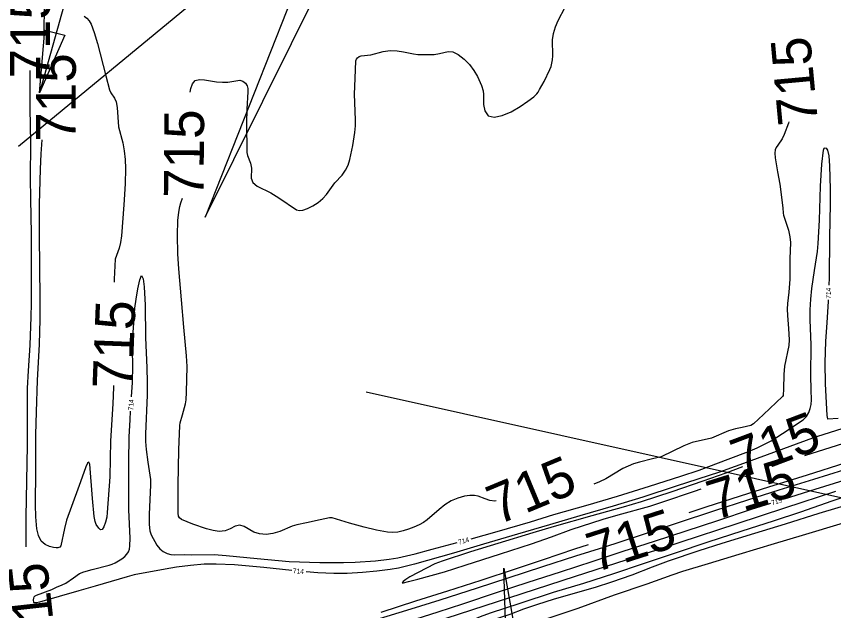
# Model space of a CAD drawing. Extents: x -468563856 to 36492962, y -306094093 to 11899197.
# Drawn here: x 1821764 to 1822443, y 531121 to 531615 of the extents above; entities that cross this region are included whole.
import ezdxf

# ---------------------------------------------------------------- set-up
doc = ezdxf.new("R2010")
doc.units = 0
for name, color, linetype in [('DT_X_Contour_Minor', 7, 'Continuous'), ('Level 14', 7, 'Continuous'), ('Level 19', 7, 'Continuous'), ('Level 40', 7, 'Continuous'), ('SH_Text', 7, 'Continuous')]:
    doc.layers.add(name, color=color, linetype=linetype)

msp = doc.modelspace()

# ---------------------------------------------------------------- linework, layer by layer
at = {"layer": 'DT_X_Contour_Minor'}
for points in [[(1821787.24, 531595.3), (1821787.25, 531596.38), (1821787.46, 531628.02)], [(1821908.51, 531551.65), (1821908.92, 531554.5), (1821910.29, 531558.61), (1821912.61, 531561.28), (1821916.06, 531562.18), (1821920.4, 531561.82), (1821930.38, 531560.22), (1821935.33, 531559.85), (1821939.83, 531559.99), (1821949.68, 531561.52), (1821952.22, 531560.68), (1821954.32, 531559.04), (1821955.74, 531556.94), (1821956.35, 531554.61), (1821956.36, 531551.73), (1821955.51, 531537.41), (1821955.32, 531526.08), (1821955.52, 531501.55), (1821956.19, 531499.05), (1821958.6, 531492.51), (1821959.31, 531488.53), (1821959.21, 531480.09), (1821960.5, 531476.44), (1821963.97, 531473.57), (1821975.51, 531467.87), (1821982.15, 531463.89), (1821996.74, 531453.97), (1821999.27, 531453.21), (1822002.05, 531453.59), (1822005.9, 531454.92), (1822010.39, 531457.05), (1822014.83, 531459.87), (1822018.61, 531463.19), (1822021.61, 531466.6), (1822028.71, 531476.2), (1822034.54, 531482.67), (1822037.43, 531486.67), (1822039.59, 531491), (1822041.14, 531495.78), (1822043.52, 531507.18), (1822045.24, 531518.04), (1822045.78, 531523.5), (1822045.74, 531528.63), (1822044.98, 531550), (1822045.34, 531563.04), (1822046, 531577.75), (1822046.5, 531579.03), (1822047.42, 531580.19), (1822048.74, 531581.12), (1822050.38, 531581.7), (1822058.48, 531582.7), (1822068.8, 531585.3), (1822074.66, 531586.13), (1822080.34, 531585.96), (1822085.58, 531585.11), (1822093.98, 531583.38), (1822097.54, 531582.96), (1822106.1, 531582.74), (1822111.05, 531582.99), (1822115.63, 531583.66), (1822122.79, 531585.46), (1822126.52, 531585.04), (1822131.03, 531582.81), (1822135.89, 531579.11), (1822140.43, 531574.49), (1822144.13, 531569.51), (1822146.95, 531564.64), (1822150.34, 531557.01), (1822151.64, 531552.78), (1822151.95, 531549.65), (1822152.11, 531541.47), (1822153.11, 531535.99), (1822155.81, 531531.95), (1822160.78, 531530.79), (1822167.44, 531532.19), (1822174.92, 531535.38), (1822182.36, 531539.6), (1822188.92, 531543.99), (1822193.79, 531547.72), (1822196.45, 531550.15), (1822197.53, 531551.6), (1822198.51, 531553.67), (1822202.34, 531560.47), (1822207.15, 531570.4), (1822208.1, 531572.97), (1822208.78, 531575.56), (1822209.24, 531578.48), (1822209.47, 531581.85), (1822209.31, 531595.09), (1822210.03, 531600.35), (1822211.75, 531605.79), (1822214.05, 531611.03), (1822219.8, 531622.07)], [(1821820.38, 531614.78), (1821822.55, 531612.98), (1821824.56, 531610.96), (1821826.29, 531608.02), (1821828.84, 531601.16), (1821831.36, 531591.98), (1821838.45, 531565.27), (1821841.44, 531553.66), (1821842.58, 531551.03), (1821845.72, 531546.7), (1821847.06, 531543.49), (1821847.84, 531538.82), (1821848.97, 531522.69), (1821852.5, 531509.48), (1821853.74, 531502.84), (1821854.48, 531495.53), (1821854.77, 531488.13), (1821854.6, 531475.45), (1821853.47, 531458.08), (1821851.46, 531432.18), (1821850.61, 531426.82), (1821849.41, 531421.97), (1821846.22, 531412.79), (1821845.32, 531396.11), (1821845.28, 531393.87)], [(1821775.34, 531569.64), (1821775.25, 531553.19), (1821775.25, 531538.03), (1821775.75, 531509.5), (1821775.61, 531480.22), (1821775.79, 531462.92), (1821776.29, 531433.8), (1821776.49, 531405.07), (1821776.35, 531375.95), (1821776.25, 531364.83), (1821775.22, 531341.52), (1821773.88, 531320.01), (1821773.14, 531305.57), (1821773.06, 531286.82), (1821773.04, 531258.18), (1821772.58, 531228.63), (1821771.9, 531198.39), (1821772.09, 531173.85)], [(1822405.67, 531527.01), (1822405.3, 531525.71), (1822401.84, 531516.46), (1822400.01, 531512.72), (1822396.54, 531507.51), (1822395.18, 531505.55), (1822394.24, 531503.57), (1822393.84, 531500.96), (1822394.1, 531497.05), (1822396.24, 531485.48), (1822398.24, 531475.22), (1822400.49, 531455.49), (1822400.86, 531451.01), (1822401.24, 531449.3), (1822405.25, 531436.82), (1822406.48, 531431.39), (1822406.87, 531426.72), (1822406.34, 531413.14), (1822406.43, 531396.2), (1822405.71, 531385.38), (1822404.61, 531376.15), (1822404.32, 531371.4), (1822404.41, 531366.14), (1822405.27, 531355.35), (1822405.71, 531350.51), (1822405.88, 531345.91), (1822405.53, 531341.21), (1822402.09, 531324), (1822401.42, 531317.07), (1822401.08, 531305.18), (1822400.92, 531299.64), (1822400.25, 531298.77), (1822384.55, 531283.79), (1822376.2, 531275.93), (1822374.13, 531274.67), (1822366.95, 531273.14), (1822361.27, 531271.85), (1822355.47, 531270.11), (1822341.32, 531264.13), (1822325.19, 531260.53), (1822318.29, 531257.75), (1822299.68, 531248.73), (1822292.25, 531246.93), (1822281.49, 531244.28), (1822276.63, 531242.76), (1822272.19, 531241), (1822267.85, 531238.83), (1822253.59, 531230.37), (1822248.44, 531227.81), (1822243.73, 531225.86)], [(1821844.84, 531307.94), (1821844.86, 531306.38), (1821844.22, 531292.62), (1821842.23, 531262.06), (1821841.64, 531232.12), (1821839.64, 531202.28), (1821839.11, 531198.46), (1821838.13, 531194.3), (1821836.82, 531190.52), (1821835.37, 531188.18), (1821833.95, 531187.99), (1821832.62, 531189.27), (1821830.4, 531192.56), (1821829.49, 531194.81), (1821828.67, 531199.01), (1821827.21, 531214.03), (1821825.08, 531242.47), (1821824.38, 531244.31), (1821823.23, 531243.27), (1821821.82, 531240.25), (1821817.4, 531228.01), (1821815.26, 531221.69), (1821805.78, 531196.05), (1821803.98, 531189.04), (1821801.05, 531174.84), (1821800.08, 531173.61), (1821798.69, 531173.12), (1821797.26, 531173.1), (1821794.95, 531173.38), (1821791.64, 531174.1), (1821787.95, 531175.7), (1821784.7, 531178.69), (1821782.51, 531183.32), (1821781.25, 531188.83), (1821780.27, 531198.81), (1821780.13, 531208.77), (1821780.21, 531237.36), (1821780.4, 531266.8), (1821780.75, 531286), (1821781.77, 531311.94), (1821783.21, 531342.35), (1821783.79, 531362.65), (1821783.76, 531380.37), (1821783.57, 531406.32), (1821783.45, 531432.48), (1821783.43, 531458.63), (1821784.12, 531487.67), (1821784.63, 531500.47), (1821785.45, 531512.07)], [(1822141.86, 531180.57), (1822163.32, 531186.61), (1822191.15, 531194.69), (1822210.54, 531200.63), (1822239.03, 531208.78), (1822263.34, 531215.89), (1822289.98, 531224.16), (1822315.78, 531232.45), (1822331.14, 531237.68), (1822355.29, 531246.71), (1822371.97, 531252.98), (1822379.19, 531256.05), (1822385.43, 531259.06), (1822390.9, 531262.05), (1822400.36, 531268.08), (1822417.35, 531279.29), (1822420.13, 531282.26), (1822422.08, 531285.4), (1822423.34, 531288.72), (1822424.05, 531292.22), (1822424.35, 531295.94), (1822424.2, 531304.41), (1822423.92, 531316.33), (1822424.11, 531341.73), (1822423.22, 531362.4), (1822423.4, 531370.68), (1822423.93, 531379.65), (1822424.74, 531388.49), (1822426.81, 531403.37), (1822429.43, 531419.12), (1822430.07, 531425.85), (1822431.13, 531445.25), (1822431.79, 531473.53), (1822433, 531491.66), (1822434.29, 531503.52), (1822434.87, 531505.07), (1822435.62, 531505.28), (1822436.62, 531505.02), (1822437.72, 531503.29), (1822438.71, 531498.64), (1822439.41, 531490.29), (1822440.04, 531470.93), (1822439.98, 531458.84), (1822439.34, 531430.85), (1822438.95, 531397.28), (1822438.73, 531391.13)], [(1822162.6, 531212.01), (1822161.46, 531211.9), (1822157.16, 531212.47), (1822153.55, 531213.68), (1822147.55, 531216.02), (1822144.5, 531216.55), (1822140.8, 531216.53), (1822136.16, 531215.86), (1822130.85, 531214.42), (1822125.3, 531212.04), (1822119.94, 531208.69), (1822115.08, 531204.9), (1822105.25, 531196.18), (1822102.28, 531194.14), (1822098.53, 531192.13), (1822094.18, 531190.2), (1822089.64, 531188.47), (1822085.22, 531187.08), (1822080.9, 531186.14), (1822076.63, 531185.76), (1822072.32, 531186.01), (1822063.26, 531187.72), (1822053.01, 531190.1), (1822040.63, 531193.61), (1822026.4, 531197.94), (1822024.08, 531198.03), (1822016.31, 531196.29), (1822005.13, 531193.69), (1821997.1, 531192.15), (1821993.16, 531190.94), (1821982.86, 531186.72), (1821977.11, 531184.94), (1821971.47, 531184.19), (1821966.15, 531184.58), (1821961.33, 531186.08), (1821953.28, 531190.79), (1821949.58, 531191.86), (1821945.78, 531190.92), (1821941.74, 531188.9), (1821937.39, 531187.13), (1821932.65, 531186.64), (1821927.5, 531187.35), (1821921.95, 531188.87), (1821910.6, 531192.84), (1821901.27, 531196.72), (1821899.48, 531197.99), (1821898.66, 531199.28), (1821898.48, 531201.76), (1821898.57, 531225.19), (1821899.11, 531254.43), (1821899.88, 531274.66), (1821900.19, 531277), (1821902.04, 531283.61), (1821904.53, 531292.56), (1821905.17, 531295.86), (1821905.54, 531302.25), (1821905.97, 531323.64), (1821905.27, 531332.66), (1821903.11, 531356.38), (1821901.34, 531379), (1821898.99, 531404.77), (1821898.22, 531417.18), (1821897.95, 531432.74), (1821898.34, 531444.93), (1821899.08, 531451.76), (1821899.87, 531456.49), (1821900.65, 531459.54), (1821902.21, 531463.62)], [(1821859.79, 531298.45), (1821860.58, 531310.28), (1821860.73, 531324.49), (1821860.52, 531337.24), (1821861.13, 531351.84), (1821862.61, 531372.12), (1821863.54, 531379.62), (1821864.94, 531388.27), (1821866.57, 531395.79), (1821868.1, 531399.23), (1821869.29, 531396.61), (1821870.12, 531389.84), (1821870.96, 531374.76), (1821871.49, 531347.79), (1821872.41, 531322.58), (1821872.85, 531310.58), (1821872.65, 531299.99), (1821871.27, 531267.73), (1821871.3, 531261.42), (1821871.85, 531254.74), (1821873.3, 531244.19), (1821875.37, 531229.79), (1821875.48, 531225.42), (1821874.48, 531200.64), (1821874.49, 531192.45), (1821875.05, 531187.16), (1821876.07, 531183.96), (1821880.9, 531175.23), (1821883.23, 531172.27), (1821886.08, 531169.98), (1821889.25, 531168.42), (1821892.45, 531167.56), (1821895.5, 531167.31), (1821903.78, 531167.55), (1821909.67, 531167.34), (1821928.35, 531167.53), (1821938.44, 531166.73), (1821964.12, 531164.16), (1821990.55, 531161.76), (1822016.22, 531160.97), (1822035.88, 531160.81), (1822045.42, 531161.03), (1822062.33, 531162.21), (1822073.59, 531163.56), (1822080.84, 531164.85), (1822095.19, 531168.11), (1822109.52, 531171.87), (1822130.28, 531177.43)], [(1822322.87, 531202.48), (1822336.81, 531207.01), (1822365.37, 531216.17), (1822388.93, 531223.69), (1822421, 531233.73), (1822452.26, 531243.68), (1822481.68, 531253.08), (1822514.64, 531263.6), (1822539.51, 531271.47), (1822570.49, 531281.53), (1822598.74, 531290.73), (1822624.33, 531299.06), (1822655.31, 531309.53), (1822683.2, 531319.25), (1822708.28, 531327.91), (1822740.17, 531338.35), (1822768.69, 531347.69), (1822794.6, 531356.17), (1822825.94, 531366.22), (1822854.4, 531375.36), (1822879.45, 531383.5), (1822889, 531386.64)], [(1822916.04, 531379.03), (1822912.4, 531377.88), (1822886.75, 531369.58), (1822859.99, 531360.88), (1822834.76, 531352.82), (1822802.38, 531342.4), (1822795.74, 531340.2), (1822766.06, 531331.14), (1822737.42, 531322.01), (1822709.4, 531312.99), (1822679.09, 531303.03), (1822651.2, 531293.87), (1822621.81, 531284.49), (1822593.01, 531275.06), (1822564.14, 531265.62), (1822535.53, 531256.41), (1822506.87, 531247.23), (1822479.66, 531238.22), (1822451.29, 531229.02), (1822427.15, 531221.52), (1822401.81, 531213.59)], [(1822438.29, 531379.14), (1822438.25, 531378), (1822437.16, 531359.99), (1822436.09, 531344.62), (1822435.52, 531326.86), (1822435.8, 531309.39), (1822437.27, 531283), (1822437.75, 531280.24), (1822438.09, 531280.09), (1822446.43, 531280.76)], [(1822419, 531249.64), (1822430.24, 531253.3), (1822450.44, 531259.76), (1822479.49, 531269.06), (1822508.08, 531278.13), (1822538.61, 531287.87), (1822568.86, 531297.55), (1822599.12, 531307.3), (1822616.53, 531313.24), (1822648.77, 531324.28), (1822679.48, 531334.41), (1822706.41, 531343.45), (1822730.03, 531351.17), (1822759, 531360.25), (1822783.74, 531368.07)], [(1821992.96, 531154.24), (1821969.56, 531156.72), (1821945.33, 531158.81), (1821930, 531159.39), (1821920.13, 531159.34), (1821908.69, 531158.44), (1821897.06, 531157.04), (1821887.56, 531155.4), (1821862.06, 531150.48), (1821856.12, 531149.02), (1821829.48, 531141.2), (1821816.11, 531137.32), (1821799.59, 531132.65), (1821783.39, 531127.87), (1821780.76, 531127.3), (1821779.25, 531127.25), (1821778.61, 531127.71), (1821778.39, 531129.81), (1821778.51, 531131.12), (1821778.88, 531132.29), (1821779.63, 531133.13), (1821780.9, 531133.78), (1821793.54, 531138.36), (1821797.34, 531140.26), (1821802.23, 531142.27), (1821805.16, 531143.82), (1821811.44, 531148.26), (1821816.57, 531151.63), (1821820.24, 531153.03), (1821826.95, 531154.96), (1821841.15, 531158.6), (1821843.63, 531159.46), (1821846.09, 531160.58), (1821851.65, 531163.94), (1821854.12, 531165.86), (1821855.95, 531167.75), (1821857.2, 531169.74), (1821858, 531172.04), (1821858.46, 531174.78), (1821858.65, 531181.03), (1821857.6, 531204.49), (1821857.53, 531217.97), (1821857.65, 531244.55), (1821857.82, 531265.21), (1821858.51, 531279.26), (1821858.99, 531286.48)], [(1822132.44, 531110.25), (1822145.7, 531114.41), (1822149.59, 531116.1), (1822157.97, 531119.11), (1822182.56, 531127.18), (1822210.23, 531136.13), (1822235.24, 531143.64), (1822260.34, 531151.8), (1822284.89, 531160.12), (1822311.53, 531168.93), (1822338.53, 531177.94), (1822366.96, 531187.21), (1822392.98, 531195.61), (1822415.55, 531202.84), (1822441.7, 531212.02), (1822457.43, 531217.42), (1822485.67, 531226.7), (1822513.96, 531235.56), (1822541.9, 531244.31), (1822572.45, 531253.71), (1822600.65, 531262.79), (1822628.9, 531272.08), (1822654.94, 531280.76), (1822671.39, 531286.17)], [(1822455.72, 531273.81), (1822428.5, 531265.23), (1822425.11, 531264.17), (1822406.5, 531257.25), (1822374.05, 531245.22), (1822347.87, 531236.04), (1822312.06, 531224.15), (1822284.26, 531215.04), (1822259.63, 531207.64), (1822231.93, 531199.61), (1822206.71, 531192.22), (1822180.2, 531184.34), (1822151.91, 531176.07), (1822127.16, 531168.61), (1822094.78, 531159.55), (1822081.49, 531156.19), (1822074.47, 531154.94), (1822063.39, 531153.54), (1822051.53, 531152.53), (1822038.83, 531151.86), (1822027.78, 531151.86), (1822014.52, 531152.41), (1822004.91, 531153.16)], [(1822451.09, 531237.66), (1822425.97, 531229.73), (1822397.32, 531220.92), (1822371.29, 531212.64), (1822343.96, 531203.86), (1822312.87, 531193.61), (1822281.22, 531183.05), (1822251.62, 531173.44), (1822228.43, 531166.15), (1822200.9, 531157.19), (1822172.17, 531147.85), (1822146.73, 531139.54), (1822115.83, 531129.58), (1822091.67, 531122.23), (1822061.68, 531112.93), (1822036.58, 531104.94), (1822007.99, 531094.5), (1821998.97, 531091.41), (1821971.29, 531083.21), (1821954.8, 531077.96), (1821925.41, 531068.03), (1821898.18, 531059), (1821874.87, 531051.43), (1821847.61, 531042.99)], [(1822367.1, 531240.27), (1822353.22, 531235.07), (1822334.07, 531228.52), (1822308.56, 531219.66), (1822282.89, 531211.38), (1822267.98, 531206.96), (1822241.98, 531199.75), (1822210.67, 531190.87), (1822192.94, 531185.47), (1822164.05, 531176.65), (1822141.11, 531169.67), (1822117.67, 531161.93), (1822111.63, 531159.62), (1822090.92, 531148.87), (1822087.49, 531146.76), (1822085.26, 531145.09), (1822084.56, 531144.08), (1822085.51, 531143.91), (1822089.79, 531144.95), (1822097.49, 531147.13), (1822119.66, 531153.11), (1822136.73, 531158.53), (1822166.23, 531168.17), (1822191.9, 531176.29), (1822208.55, 531182.31), (1822224.88, 531188.17), (1822251.44, 531196.8), (1822263.82, 531200.49), (1822290.13, 531207.79), (1822300.94, 531211.25), (1822327.18, 531220.08), (1822332.81, 531221.96)], [(1822390.37, 531209.96), (1822374.4, 531204.87), (1822346.31, 531195.61), (1822319.96, 531186.97), (1822293.76, 531178.31), (1822267.78, 531169.88), (1822242.79, 531161.78), (1822215.73, 531152.9), (1822188.84, 531144.17), (1822163.48, 531135.96), (1822134.64, 531126.33), (1822114.03, 531119.54), (1822084.57, 531110.22), (1822055.85, 531101), (1822027.7, 531091.72), (1822000.77, 531082.85), (1821971.55, 531073.36), (1821942.62, 531064.04), (1821921.62, 531057.31)], [(1822462.06, 531210.89), (1822430.53, 531201.7), (1822402.62, 531192.71), (1822377.11, 531184.99), (1822350.02, 531176.7), (1822330.87, 531170.59), (1822305.34, 531162.02), (1822292.11, 531157.05), (1822275.26, 531150.3), (1822258.28, 531144.41), (1822244.67, 531140), (1822228.28, 531135.36), (1822209.84, 531130.07), (1822196.74, 531125.99), (1822185.22, 531121.96), (1822173.88, 531117.8), (1822154.26, 531111.38), (1822140.51, 531106.9), (1822132.67, 531104.27)], [(1822132.63, 531091.28), (1822142.54, 531094.32), (1822161.67, 531100.32), (1822185.92, 531108.05), (1822213.28, 531117), (1822230.57, 531122.82), (1822260.92, 531133.96), (1822287.86, 531143.13), (1822308.78, 531150.57), (1822317.45, 531153.55), (1822338.87, 531160.16), (1822364.37, 531167.87), (1822393.59, 531176.61), (1822417.02, 531183.69), (1822450.89, 531193.89)], [(1822066.95, 531119.71), (1822095.94, 531128.96), (1822122.43, 531137.2), (1822150.13, 531146.07), (1822178.48, 531155.5), (1822201.96, 531163.4), (1822227.89, 531172.16), (1822239.21, 531175.72)]]:
    msp.add_lwpolyline(points, dxfattribs=at)
at = {"layer": 'Level 14'}
msp.add_lwpolyline([(1822444.29, 531219.73), (1822402.07, 531205.86), (1822362.27, 531192.96), (1822315.04, 531177.42), (1822270.18, 531162.88), (1822228.03, 531149.28), (1822183.88, 531134.78), (1822142.19, 531121.34), (1822099.37, 531107.28), (1822054.26, 531092.67), (1822008.51, 531077.84), (1821962.66, 531063), (1821916.5, 531048.08), (1821870, 531032.72), (1821825.04, 531018.18), (1821780.22, 531003.71), (1821737.66, 530989.77), (1821648.73, 530960.74), (1821601.95, 530945.47), (1821553.57, 530929.66), (1821503.52, 530913.42), (1821454.26, 530897.29), (1821404.04, 530881.11)], dxfattribs=at)
at = {"layer": 'Level 40'}
for p, q in [((1821765.78, 531506.68), (1822179.21, 531848.1)), ((1821844.75, 531770.53), (1821783.22, 531551.11)), ((1821783.22, 531551.11), (1821787.84, 531603.18)), ((1821787.84, 531603.18), (1821804.47, 531598.88)), ((1821804.47, 531598.88), (1821783.22, 531551.11)), ((1822054.52, 531302.57), (1822761.52, 531145.03))]:
    msp.add_line(p, q, dxfattribs=at)
at = {"layer": 'SH_Text'}
for points in [[(1822137.86, 531997.39), (1821920.95, 531447.79), (1822159.96, 531929.3)], [(1822184.44, 530662.05), (1822168.94, 531156.04), (1822252.12, 530684.02)]]:
    msp.add_lwpolyline(points, close=True, dxfattribs=at)

# ---------------------------------------------------------------- texts
at = {"layer": 'Level 19'}
for s, height, rotation, p in [('715', 33, 89.60487, (1821791.78, 531562.77)), ('715', 33, 95.28288, (1822429.9, 531525.55)), ('715', 33, 89.94291, (1821813.45, 531510.3)), ('715', 33, 89.58195, (1821919.55, 531463.55)), ('714', 4, 87.9261, (1822440.32, 531379.85)), ('715', 33, 87.7313, (1821860.24, 531304.54)), ('714', 4, 86.18431, (1821861.04, 531287.13)), ('715', 33, 20.61502, (1822365.46, 531230.27)), ('715', 33, 22.57454, (1822163.83, 531191.76)), ('715', 33, 17.26322, (1822344, 531195.77)), ('719', 4, 17.68148, (1822391.69, 531208.28)), ('715', 33, 17.78461, (1822244.44, 531152.33)), ('714', 4, 14.98858, (1822131.55, 531175.7)), ('715', 33, 96.34285, (1821797.58, 531088.97)), ('714', 4, 355.52031, (1821993.58, 531152.05))]:
    msp.add_text(s, height=height, rotation=rotation, dxfattribs=at).set_placement(p)

doc.saveas('drawing.dxf')
